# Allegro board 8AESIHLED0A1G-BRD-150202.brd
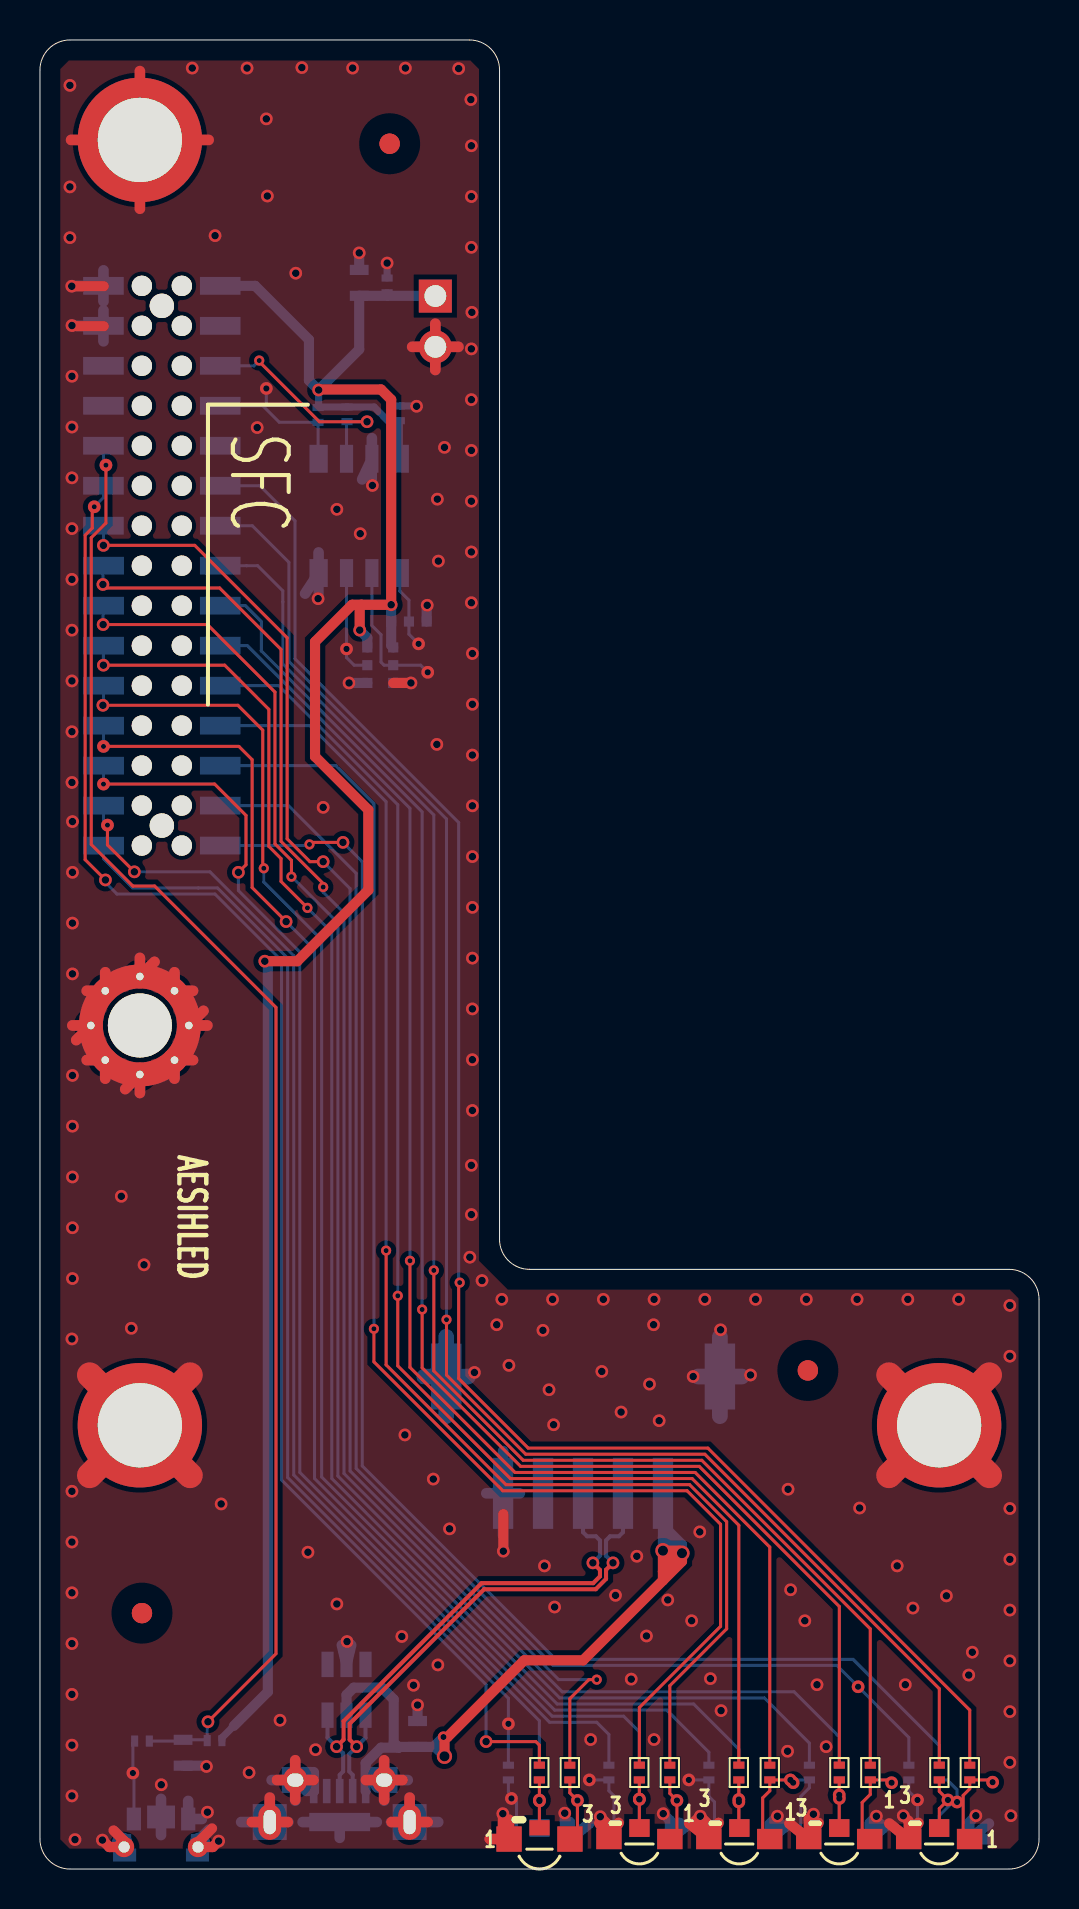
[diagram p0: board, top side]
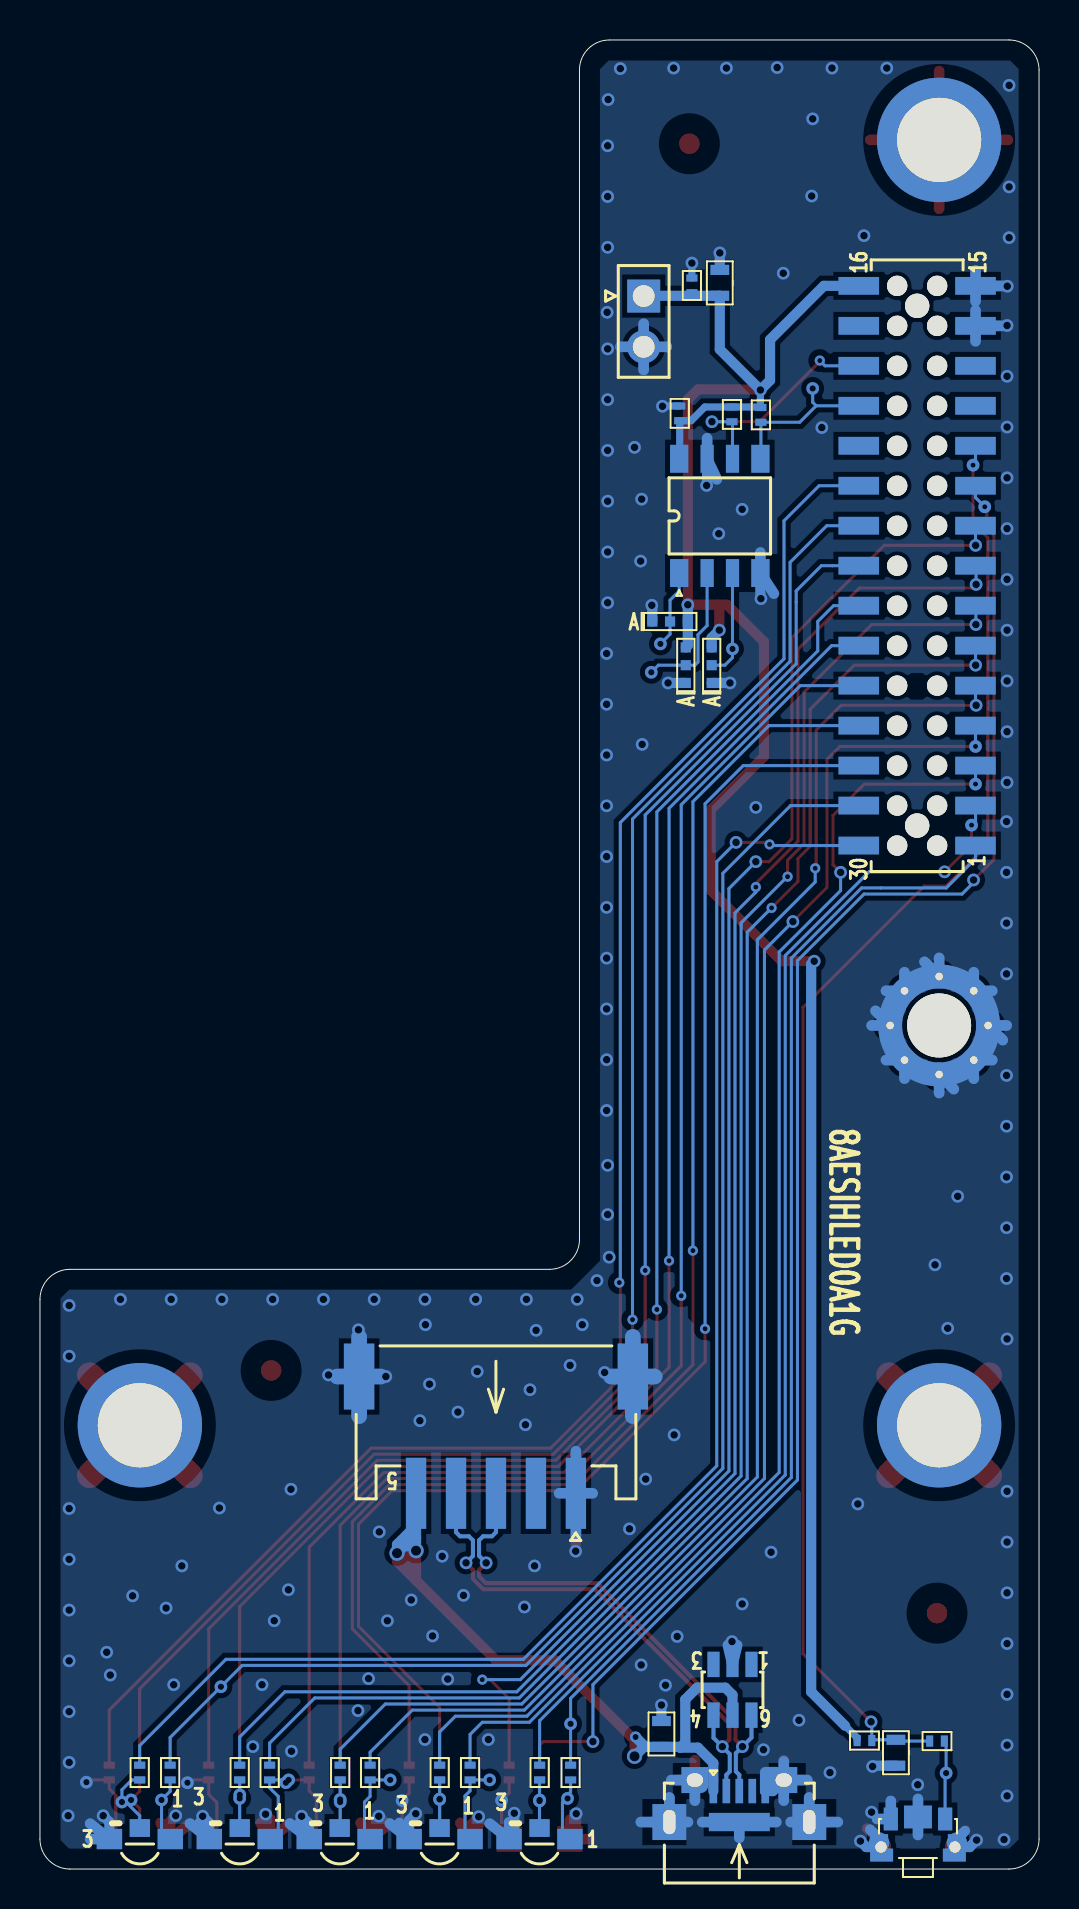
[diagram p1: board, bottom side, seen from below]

Outline 50 x 91.5 mm; copper layers: TOP, BOTTOM. Coordinates in mm from the lower left corner of the outline.
Outline path: 0,90 0,1.5 arc(0.44,0.44) 1.5,0 48.5,0 arc(49.56,0.44) 50,1.5 50,28.5 arc(49.56,29.56) 48.5,30 24.5,30 arc(23.44,30.44) 23,31.5 23,90 arc(22.56,91.06) 21.5,91.5 1.5,91.5 arc(0.44,91.06) 0,90

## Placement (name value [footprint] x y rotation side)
A1  3.5mm_8via  [A126_FG]  5 42.2 0 top
B1  Optics  [2B]  17.5 86.31 0 top
B2  Optics  [2B]  38.43 24.94 0 top
B3  Optics  [2B]  5.11 12.8 0 top
C1  10uF 6.3V***  [C0603]  15.98 79.35 270 bottom
C2  0.1u 16V***  [C0402]  17.37 79.22 270 bottom
C3  0.1u 16V***  [C0402]  17.98 72.82 270 bottom
C4  0.1uF 25V  [C0603]  18.9 6.76 90 bottom
C5  1uF 25V  [C0603]  7.16 5.82 270 bottom
D1  LED (Y/G)  [LED_LG110]  30 1.5 0 top
D2  LED (Y/G)  [LED_LG110]  35 1.5 0 top
D3  LED (Y/G)  [LED_LG110]  40 1.5 0 top
D4  LED (Y/G)  [LED_LG110]  45 1.5 0 top
D5  KPBVA-3010QBDCGKC  [KPBA_3010_A]  25 1.5 0 top
D6  LED (Y/G)  [LED_LG110]  35 1.5 180 bottom
D7  LED (Y/G)  [LED_LG110]  30 1.5 180 bottom
D8  LED (Y/G)  [LED_LG110]  25 1.5 180 bottom
D9  LED (Y/G)  [LED_LG110]  45 1.5 180 bottom
D10  LED (Y/G)  [LED_LG110]  40 1.5 180 bottom
J1  1K 5% 1/16W***  [JP3_0402]  18.47 62.41 180 bottom
J2  1K 5% 1/16W***  [JP3_0402]  17.68 60.22 90 bottom
J3  1K 5% 1/16W***  [JP3_0402]  16.38 60.22 90 bottom
JP1  **HEADER PIN C2(S)  [JP2]  19.79 78.69 270 bottom
JP2  HEADER PIN 2*15  [IC_JP2X15_2P0_SMD]  5.1 51.2 90 bottom
JP3  WAFER PIN 5P  [P200_5_R_SMT]  27.18 21.84 0 bottom
NOREF  -  []  8.41 73.25 270 top
NOREF#2  -  []  -46.9 94.25 0 top
NOREF#3  -  []  10.52 23.39 90 top
NOREF#4  -  []  0 0 0 top
O1  3.5mm_8via  [PAD_C245D166]  5 86.5 180 bottom
O2  3.5mm_8via  [PAD_C245D166]  45 22.2 180 bottom
O3  3.5mm_8via  [PAD_C245D166]  5 22.2 180 bottom
P1  UN15111-N12A41-7H  [USB_MICRO_B_DIP_F]  15 2.35 180 bottom
R1  150 5% 1/16W  [R0402]  24.99 4.83 270 top
R2  150 5% 1/16W  [R0402]  26.52 4.83 270 top
R3  150 5% 1/16W  [R0402]  30 4.83 270 top
R4  150 5% 1/16W  [R0402]  31.52 4.83 270 top
R5  150 5% 1/16W  [R0402]  34.98 4.83 270 top
R6  150 5% 1/16W  [R0402]  36.53 4.83 270 top
R7  150 5% 1/16W  [R0402]  40.01 4.83 270 top
R8  150 5% 1/16W  [R0402]  41.55 4.83 270 top
R9  150 5% 1/16W  [R0402]  45.01 4.83 270 top
R10  150 5% 1/16W  [R0402]  46.53 4.83 270 top
R11  4.7K 5% 1/16W***  [R0402]  15.37 72.77 270 bottom
R12  4.7K 5% 1/16W***  [R0402]  13.92 72.75 270 bottom
R13  1K 5% 1/16W  [R0402]  8.74 6.43 180 bottom
R14  150 5% 1/16W  [R0402]  45.01 4.83 270 bottom
R15  150 5% 1/16W  [R0402]  43.48 4.83 270 bottom
R16  150 5% 1/16W  [R0402]  40.01 4.83 270 bottom
R17  150 5% 1/16W  [R0402]  38.51 4.83 270 bottom
R18  150 5% 1/16W  [R0402]  34.98 4.83 270 bottom
R19  150 5% 1/16W  [R0402]  33.48 4.83 270 bottom
R20  150 5% 1/16W  [R0402]  30 4.83 270 bottom
R21  150 5% 1/16W  [R0402]  28.47 4.83 270 bottom
R22  150 5% 1/16W  [R0402]  24.99 4.83 270 bottom
R23  150 5% 1/16W  [R0402]  23.44 4.83 270 bottom
R24  68R 5% 1/16W  [R0402]  5.11 6.4 180 bottom
SW1  TSS00-EG-200-T28  [SW_TS_308GS]  6.06 1.53 180 bottom
U1  AT24C02D-SSHM-T***  [SOP8_1P27_6]  15.98 67.69 180 bottom
U2  SRV05-4  [SOT_26]  15.34 8.97 0 bottom

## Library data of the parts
A1 = SCREW HOLE_6: Tolerance: ***; User Part Number: ***; room: SCREW
B1-B3 = Optics_solder: Tolerance: ***; User Part Number: ***
C1-C4 = CAP_NP: Tolerance: ***; User Part Number: ***
C5 = CAP_NP: Tolerance: ***; User Part Number: ***; room: CPU_3_3V
D1-D4 D6-D10 = LED2A_1_4: Tolerance: ***; User Part Number: ***
D5 = LED2A_1_3: Tolerance: ***; User Part Number: ***
J1-J3 = JP3_0603: Tolerance: ***; User Part Number: ***
JP1 = JP2_0: Tolerance: ***; User Part Number: ***
JP2 = 30G2_0: Tolerance: ***; User Part Number: ***
JP3 = JP5_2: Tolerance: ***; User Part Number: ***
O1-O3 = SCREW HOLE_0: Tolerance: ***; User Part Number: ***; room: SCREW
P1 = UN15111_N12A41_7H: Tolerance: ***; User Part Number: ***
R1-R24 = R: Tolerance: ***; User Part Number: ***
SW1 = SW_BTS_1: Tolerance: ***; User Part Number: ***
U1 = AT24C512: Tolerance: ***; User Part Number: ***
U2 = SRV05: Tolerance: ***; User Part Number: ***

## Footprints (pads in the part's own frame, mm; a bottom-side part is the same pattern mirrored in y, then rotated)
2B
  round 1.016 smd: 1(0,0) 2(0,0)
A126_FG
  round 3.2 hole 3.2 unplated: (0,0)
  round 1.194 hole 0.381: 2(1.732,1.732) 3(-1.732,1.732) 4(-1.732,-1.732) 5(1.732,-1.732) 6(0,2.451) 7(0,-2.451) 8(-2.451,0) 9(2.451,0)
C0402
  rect 0.356x0.559 smd: 1(-0.368,0) 2(0.368,0)
C0603
  rect 0.508x0.94 smd: 1(-0.648,0) 2(0.648,0)
IC_JP2X15_2P0_SMD
  round 1.016 hole 1.016 unplated: (0,0) (0,2) (2,0) (2,2) (4,0) (4,2) (6,0) (6,2) (8,0) (8,2) (10,0) (10,2) (12,0) (12,2) (14,0) (14,2) (16,0) (16,2) (18,0) (18,2) (20,0) (20,2) (22,0) (22,2) (24,0) (24,2) (26,0) (26,2) (28,0) (28,2)
  round 1.219 hole 1.219 unplated: (1,1) (27,1)
  rect 0.889x2.032 smd: 1(0,-1.921) 2(2,-1.921) 3(4,-1.921) 4(6,-1.921) 5(8,-1.921) 6(10,-1.921) 7(12,-1.921) 8(14,-1.921) 9(16,-1.921) 10(18,-1.921) 11(20,-1.921) 12(22,-1.921) 13(24,-1.921) 14(26,-1.921) 15(28,-1.921) 16(28,3.921) 17(26,3.921) 18(24,3.921) 19(22,3.921) 20(20,3.921) 21(18,3.921) 22(16,3.921) 23(14,3.921) 24(12,3.921) 25(10,3.921) 26(8,3.921) 27(6,3.921) 28(4,3.921) 29(2,3.921) 30(0,3.921)
JP2
  rect 1.651x1.651 hole 1.092: 1(0,0)
  round 1.651 hole 1.092: 2(2.54,0)
JP3_0402
  rect 0.508x0.508 smd: 1(-0.889,0) 2(0,0) 3(0.889,0)
KPBA_3010_A
  rect 1.27x1.27 smd: 1(-1.524,0) 3(1.524,0)
  rect 1.016x0.762 smd: 2(0,0.559)
LED_LG110
  rect 1.27x1.016 smd: 1(1.524,0) 3(-1.524,0)
  rect 1.016x0.889 smd: 2(0,0.55)
P200_5_R_SMT
  rect 1.016x3.556 smd: 1(-4,3.048) 2(-2,3.048) 3(0,3.048) 4(2,3.048) 5(4,3.048)
  rect 1.524x3.302 smd: 6(6.85,-2.794) 7(-6.85,-2.794)
PAD_C245D166
  round 6.223 hole 4.216: 1(0,0)
R0402
  rect 0.356x0.559 smd: 1(-0.368,0) 2(0.368,0)
SOP8_1P27_6
  rect 0.914x1.397 smd: 1(-2.032,-2.857) 4(2.032,-2.857) 5(2.032,2.857) 8(-2.032,2.857)
  rect 0.66x1.397 smd: 2(-0.635,-2.857) 3(0.635,-2.857) 6(0.635,2.857) 7(-0.635,2.857)
SOT_26
  rect 0.61x1.27 smd: 1(-0.95,-1.27) 2(0,-1.27) 3(0.95,-1.27) 4(0.95,1.27) 5(0,1.27) 6(-0.95,1.27)
SW_TS_308GS
  rect 0.711x1.143 smd: 1(-1.36,0.978) 2(1.36,0.978)
  rect 1.397x1.143 smd: 3(0,1.079)
  round 1.016 hole 0.559: 4(-1.85,-0.425) 5(1.85,-0.425)
USB_MICRO_B_DIP_F
  rect 0.381x1.219 smd: 1(-1.3,1.55) 2(-0.65,1.55) 3(0,1.55) 4(0.65,1.55) 5(1.3,1.55)
  oval 1.168x1.321 hole 0.813x0.66: 6(-2.225,2.1) 7(2.225,2.1)
  oval 1.143x1.778 hole 0.61x1.219: 8(-3.5,0) 9(3.5,0)
  rect 3.048x0.914 smd: 10(0,0)

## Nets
3.3V: C1.2 C2.2 C3.2 J1.3 J2.3 J3.3 JP1.1 JP2.16 R11.1 R12.1 R13.1 U1.8(VCC)
GND: A1.2 A1.3 A1.4 A1.5 A1.6 A1.7 A1.8 A1.9 C1.1 C2.1 C3.1 C4.2 C5.2 D1.3 D2.3 D3.3 D4.3 D5.1 D6.3 D7.3 D8.3 D9.3 D10.3 J1.1 J2.1 J3.1 JP1.2 JP2.14 JP2.15 JP3.1 JP3.6 JP3.7 O1.1 O2.1 O3.1 P1.5(GND#5) P1.6(GND#6) P1.7(GND#7) P1.8(GND#8) P1.9(GND#9) P1.10(GND#10) SW1.1 SW1.3 SW1.4 SW1.5 U1.4(GND) U1.7(TEST) U2.2(GND)
VBUS: C4.1 JP3.5 P1.1(VBUS) U2.5(VCC)
A0: J1.2 U1.1(A0)
A1: J2.2 U1.2(A1)
A2: J3.2 U1.3(A2)
FP_LED0_B: JP2.10 R1.1
FP_LED0_G: JP2.9 R2.1
FP_LED1_G: JP2.2 R22.1
FP_LED1_Y: JP2.1 R23.1
FP_LED2_G: JP2.28 R3.1
FP_LED2_Y: JP2.27 R4.1
FP_LED3_G: JP2.4 R20.1
FP_LED3_Y: JP2.3 R21.1
FP_LED4_G: JP2.26 R5.1
FP_LED4_Y: JP2.25 R6.1
FP_LED5_G: JP2.6 R18.1
FP_LED5_Y: JP2.5 R19.1
FP_LED6_G: JP2.24 R7.1
FP_LED6_Y: JP2.23 R8.1
FP_LED7_G: JP2.8 R16.1
FP_LED7_Y: JP2.7 R17.1
FP_LED8_G: JP2.22 R9.1
FP_LED8_Y: JP2.21 R10.1
FP_LED9_G: JP2.30 R14.1
FP_LED9_Y: JP2.29 R15.1
FP_TACH_PB: C5.1 JP2.11 R13.2 R24.1
I2C_SCL_FP: JP2.18 R11.2 U1.6(SCL)
I2C_SDA_FP: JP2.19 R12.2 U1.5(SDA)
LED0_B: D5.2 R1.2
LED0_G: D5.3 R2.2
LED1_G: D8.2 R22.2
LED1_Y: D8.1 R23.2
LED2_G: D1.2 R3.2
LED2_Y: D1.1 R4.2
LED3_G: D7.2 R20.2
LED3_Y: D7.1 R21.2
LED4_G: D2.2 R5.2
LED4_Y: D2.1 R6.2
LED5_G: D6.2 R18.2
LED5_Y: D6.1 R19.2
LED6_G: D3.2 R7.2
LED6_Y: D3.1 R8.2
LED7_G: D10.2 R16.2
LED7_Y: D10.1 R17.2
LED8_G: D4.2 R9.2
LED8_Y: D4.1 R10.2
LED9_G: D9.2 R14.2
LED9_Y: D9.1 R15.2
TACT: R24.2 SW1.2
USB_DN: JP3.4 P1.2(DM) U2.4(I/O3)
USB_DP: JP3.3 P1.3(DP) U2.6(I/O4)

Pads without a net: B1 1 2; B2 1 2; B3 1 2; JP2 12 13 17 20; JP3 2; P1 4; U2 1 3

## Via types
v1: diameter 0.635, hole 0.318, TOP to BOTTOM, 27 vias
v2: diameter 0.635, hole 0.381, TOP to BOTTOM, 197 vias
v3: diameter 0.635, hole 0.254, TOP to BOTTOM, 5 vias
v4: diameter 0.508, hole 0.254, TOP to BOTTOM, 15 vias
v5: diameter 0.762, hole 0.508, TOP to BOTTOM, 3 vias
v6: diameter 0.559, hole 0.305, TOP to BOTTOM, 1 via

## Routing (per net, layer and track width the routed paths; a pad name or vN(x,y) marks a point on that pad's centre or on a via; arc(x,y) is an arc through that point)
3.3V: length 108.3
  TOP w0.508: v2(11.25,45.42) 12.88,45.42 16.43,48.97 16.43,52.98 13.77,55.65 13.77,61.39 15.62,63.25 16.08,63.25 ; v2(13.94,73.99) 13.97,74.02 17.07,74.02 17.58,73.51 v2(17.58,63.25) 16.08,63.25 ; 16.08,63.25 16,63.17 v2(16,61.98)
  BOTTOM w0.356: 13.94,73.14 R11.1 16.73,73.14 17.41,72.45 C3.2 17.98,70.57 ; 13.94,73.14 R12.1 ; 13.94,73.14 v2(13.94,73.99) ; C2.2 17.37,78.73 17.4,78.7 ; R13.1 9.11,6.57 9.7,7.16
  BOTTOM w0.508: JP2.16 10.77,79.2 13.46,76.5 13.46,74.47 v2(13.94,73.99) 15.98,76.02 C1.2 19.77,78.7 JP1.1 ; J2.3 17.58,61.21 J1.3 v2(17.58,63.25) ; 9.7,7.16 11.4,8.86 11.4,45.26 v2(11.25,45.42) ; v2(16,61.98) 16.38,61.59 J3.3 ; 17.98,70.57 U1.8
GND: length 212.4
  TOP w0.152: 33.48,1.78 32.94,2.31
  TOP w0.508: v2(43.21,2.67) 43.48,2.4 D4.3 ; 3.19,79.18 v2(1.59,79.18) ; v2(23.16,2.77) 23.16,1.81 D5.1 ; v2(38.71,2.74) 38.48,2.51 D3.3 ; 23.19,17.75 v2(23.19,15.9) ; 3.68,1.93 4.21,1.4 SW1.5 3.47,1.1 v2(3.12,1.45) ; J2.1 v2(18.57,59.33) ; 8.61,2.03 7.91,1.33 SW1.4 8.64,1.1 v2(8.94,1.4) ; v2(1.6,77.22) 1.64,77.18 3.19,77.18 ; D2.3 33.48,2.21 v2(33.05,2.64) ; v2(28.04,2.62) 28.48,2.18 D1.3
  TOP w0.533: v2(33.05,2.64) 32.68,2.27 32.51,2.27 D2.3 33.96,2.31 ; P1.6 17.23,5.44 ; P1.6 17.23,3.46 ; P1.6 16.31,4.45 ; P1.6 18.14,4.45 ; P1.9 11.5,3.57 ; P1.9 10.6,2.35 ; P1.9 12.4,2.35 ; 8.18,42.93 A1.9 8.38,42.2 ; 2.34,43.93 A1.3 3.27,44.86 ; 5,38.82 A1.7 4.27,39.02 ; 2.34,40.47 A1.4 3.27,39.54 ; JP1.2 19.79,77.31 ; JP1.2 20.94,76.15 ; JP1.2 19.79,74.99 ; JP1.2 18.63,76.15 ; O1.1 8.44,86.5 ; O1.1 5,83.06 ; O1.1 1.56,86.5 ; O1.1 5,89.94 ; 37.51,2.27 D3.3 38.96,2.31 ; 1.62,42.2 A1.8 1.82,41.47 ; 7.66,43.93 A1.2 6.73,44.86 ; P1.8 18.5,3.57 ; P1.8 17.6,2.35 ; P1.8 19.4,2.35 ; 11.86,4.45 P1.7 ; P1.7 12.78,3.46 ; P1.7 12.78,5.44 ; P1.7 13.69,4.45 ; 43.96,2.31 D4.3 42.51,2.27 ; 7.66,40.47 A1.5 6.73,39.54 ; 22.51,1.5 D5.1 23.48,2.47 ; 27.99,2.31 D1.3 28.96,2.31 ; 5,45.58 A1.6 5.73,45.38
  TOP w1.27: O2.1 47.51,24.71 ; O2.1 42.49,24.71 ; O2.1 47.51,19.69 ; O2.1 42.49,19.69 ; O3.1 7.51,19.69 ; O3.1 7.51,24.71 ; O3.1 2.49,24.71 ; O3.1 2.49,19.69
  BOTTOM w0.356: C3.1 18.83,73.19 v2(18.85,73.18) ; C2.1 v2(17.37,80.34)
  BOTTOM w0.508: P1.5 13.33,3.9 P1.7 ; C1.1 v2(15.98,80.85) ; v2(13.92,63.55) 13.94,63.58 U1.4 ; J1.1 19.35,63.2 v2(19.38,63.22) ; v2(36.91,2.64) 36.52,2.26 D6.3 ; J2.1 v2(18.57,59.33) ; 3.71,1.91 4.21,1.4 SW1.5 3.47,1.1 v2(3.12,1.45) ; v2(15.37,11.38) 15.34,11.35 U2.2 ; C5.2 8.29,5.17 v2(8.33,5.13) ; v2(8.94,1.4) 8.64,1.1 SW1.4 7.91,1.43 8.46,1.98 ; v2(16.64,69.22) 16.61,69.24 U1.7 ; v2(31.19,2.77) 31.52,2.44 D7.3 ; C4.2 v2(18.9,8.2) ; D10.3 41.52,2.31 v2(41.86,2.64) ; D8.3 26.26,1.76 v2(26.26,2.79) ; J3.1 v2(15.47,59.33) 15.44,59.36 ; D9.3 46.52,2.35 v2(46.84,2.67) ; 23.18,15.91 v2(23.19,15.9)
  BOTTOM w0.533: 6.73,39.54 A1.5 7.66,40.47 ; 19.79,74.99 JP1.2 ; JP1.2 19.79,77.31 ; JP1.2 18.63,76.15 ; JP1.2 20.94,76.15 ; 18.41,4.45 P1.6 17.23,3.42 ; 6.06,1.7 SW1.3 6.06,3.51 ; P1.9 11.5,3.58 ; P1.9 12.43,2.35 ; P1.9 10.07,2.35 ; 13.27,63.8 U1.4 13.94,65.86 ; JP2.15 3.18,79.98 ; JP2.15 3.18,78.42 ; JP2.15 1.83,79.2 ; JP2.14 3.18,77.98 ; JP2.14 1.83,77.2 ; JP2.14 3.18,76.42 ; 1.62,42.2 A1.8 1.82,41.47 ; 5,38.82 A1.7 4.27,39.02 ; P1.8 18.5,3.58 ; P1.8 19.93,2.35 ; P1.8 17.57,2.35 ; 3.27,44.86 A1.3 2.34,43.93 ; 32.01,2.31 D7.3 32.49,2.27 ; 8.18,42.93 A1.9 8.38,42.2 ; 42.01,2.31 D10.3 42.49,2.27 ; 26.52,2.34 D8.3 27.49,2.27 ; P1.10 16.85,2.35 ; P1.10 13.15,2.35 ; P1.10 15,1.56 ; JP3.1 23.18,20.9 ; JP3.1 24.02,18.8 ; JP3.1 22.34,18.8 ; JP3.1 23.18,16.69 ; 16.61,71.58 U1.7 16.12,69.52 ; 12.78,3.42 P1.7 ; P1.7 11.59,4.45 ; P1.7 13.17,4.84 13.55,4.84 P1.5 13.7,4.84 ; P1.7 12.78,5.38 ; 7.66,43.93 A1.2 6.73,44.86 ; 47.49,1.5 D9.3 47.49,2.27 ; 7.42,3.41 SW1.1 8.1,2.5 ; 2.34,40.47 A1.4 3.27,39.54 ; 37.01,2.31 D6.3 37.49,2.27 ; 15.11,11.2 U2.2 15.57,11.2 ; 5,45.58 A1.6 5.73,45.38
  BOTTOM w0.787: JP3.7 20.33,26.62 ; JP3.7 21.42,24.64 ; JP3.7 20.33,22.66 ; JP3.7 19.24,24.64 ; 34.03,22.66 JP3.6 ; JP3.6 32.94,24.64 ; JP3.6 34.03,26.62 ; JP3.6 35.12,24.64
  vias: v2(1.5,89.23) v2(1.5,84.15) v2(1.5,81.61) v2(1.6,74.68) v2(1.6,72.14) v2(1.6,69.6) v2(1.6,67.06) v2(1.6,64.52) v2(1.6,61.98) v2(1.6,59.44) v2(1.6,56.9) v2(1.6,54.36) v2(1.63,52.4) v2(1.63,49.86) v2(1.63,47.32) v2(1.63,44.78) v2(1.63,39.7) v2(1.63,37.16) v2(1.63,34.62) v2(1.63,32.08) v2(1.63,29.54) v2(1.6,26.52) v2(1.6,18.9) v2(1.6,16.36) v2(1.6,13.82) v2(1.6,11.28) v2(1.6,8.74) v2(1.6,6.2) v2(1.6,3.66) v2(1.75,1.47) v2(4.07,33.66) v2(4.57,27.05) v2(5.21,30.23) v2(6.07,4.22) v2(7.62,90.09) v2(8.38,2.84) v2(8.76,81.71) v2(9.07,18.26) v2(10.36,90.09) v2(10.46,4.83) v2(10.87,72.11) v2(11.33,87.55) v2(11.38,83.69) v2(12.01,7.44) v2(12.8,79.83) v2(13.11,90.12) v2(13.41,15.85) v2(13.79,5.97) v2(14.17,53.11) v2(14.86,68.02) v2(14.86,13.26) v2(15.65,90.09) v2(16.03,66.8) v2(18.11,11.63) v2(18.29,90.09) v2(18.26,21.72) v2(18.69,9.19) v2(19.68,19.51) v2(19.89,68.53) v2(19.94,65.43) v2(19.86,56.26) v2(19.91,10.21) v2(20.24,71.12) v2(20.5,17.02) v2(20.95,90.07) v2(21.51,30.61) v2(21.56,88.52) v2(21.59,86.21) v2(21.59,83.67) v2(21.59,81.13) v2(21.62,77.88) v2(21.59,76.05) v2(21.59,73.51) v2(21.59,70.97) v2(21.59,68.43) v2(21.59,65.89) v2(21.59,63.35) v2(21.64,60.81) v2(21.64,58.27) v2(21.64,55.73) v2(21.64,53.19) v2(21.64,50.65) v2(21.64,48.11) v2(21.64,45.57) v2(21.64,43.03) v2(21.64,40.49) v2(21.64,37.95) v2(21.59,35.2) v2(21.59,32.74) v2(21.74,24.84) v2(22.12,29.44) v2(22.86,27.23) v2(23.11,28.5) v2(23.47,25.2) v2(25.17,26.95) v2(25.25,15.16) v2(25.48,23.98) v2(25.65,28.5) v2(25.7,22.23) v2(25.76,13.11) v2(27.56,6.48) v2(28.12,24.89) v2(28.19,28.5) v2(28.8,13.69) v2(29.08,22.86) v2(29.59,9.5) v2(29.87,15.65) v2(30.35,11.66) v2(30.51,24.26) v2(30.73,28.5) v2(30.71,27.23) v2(30.73,6.48) v2(30.99,22.43) v2(31.42,13.46) v2(32.61,12.42) v2(32.69,24.64) v2(33.02,16.87) v2(33.27,28.5) v2(33.55,9.53) v2(34.06,26.97) v2(34.09,7.92) v2(35.56,24.71) v2(35.81,28.5) v2(37.44,19) v2(37.41,5.89) v2(37.57,13.97) v2(38.28,12.42) v2(38.35,28.5) v2(38.89,9.22) v2(39.34,6.12) v2(40.89,28.5) v2(41.02,18.06) v2(42.9,15.16) v2(43.31,9.22) v2(43.43,28.5) v2(43.69,13.06) v2(45.36,13.67) v2(45.97,28.5) v2(46.48,9.7) v2(46.66,10.85) v2(48.54,28.19) v2(48.54,25.65) v2(48.54,18.03) v2(48.54,15.49) v2(48.54,12.95) v2(48.54,10.41) v2(48.54,7.87) v2(48.54,5.33) v2(48.59,2.67)
VBUS: length 40.1
  TOP w0.508: 31.62,15.29 31.21,14.88 31.18,14.88 ; 31.62,15.29 31.62,15.85 ; 31.62,15.29 v5(32.13,15.8) ; v5(32.13,15.8) 32.01,15.93 v5(31.18,15.93) 31.18,14.88 ; v5(32.13,15.8) 32.13,15.39 31.18,14.44 ; 31.18,14.88 31.18,14.44 ; 31.18,14.44 27.18,10.44 24.23,10.44 20.4,6.6 v6(20.19,6.6) 20.24,6.55 v5(20.24,5.64)
  BOTTOM w0.508: 17.96,6.07 18,6.11 C4.1 19.7,6.11 ; 17.96,6.07 17.7,6.32 17.7,8.48 17.12,9.07 15.7,9.07 15.34,8.71 U2.5 ; 17.96,6.07 17.07,6.07 16.3,5.3 P1.1 ; JP3.5 31.18,17.18 ; 31.18,17.18 32.13,16.23 v5(32.13,15.8) 31.78,16.15 31.6,16.15 31.18,16.57 ; 31.18,17.18 31.18,16.57 ; 19.7,6.11 19.77,6.11 v5(20.24,5.64) ; 19.7,6.11 v6(20.19,6.6) ; 31.18,16.57 v5(31.18,15.93)
A0: length 3.9
  BOTTOM w0.152: U1.1 18.01,63.93 18.47,63.47 J1.2 18.47,61.77 v1(18.95,61.29)
A1: length 7.2
  BOTTOM w0.152: U1.2 16.61,62.2 17.07,61.75 17.07,60.38 17.22,60.22 J2.2 19.05,60.22 v1(19.41,59.87)
A2: length 5.4
  BOTTOM w0.152: U1.3 v1(15.34,61.04) 15.34,60.6 15.72,60.22 J3.2
FP_LED0_B: length 78.1
  TOP w0.152: v2(22.33,6.38) 24.82,6.38 24.99,6.2 R1.1 ; v3(2.72,68.15) 2.62,68.05 2.62,67.08 2.26,66.73 2.26,50.5 v2(3.28,49.48)
  BOTTOM w0.152: JP2.10 3.18,68.61 v3(2.72,68.15) ; v2(3.28,49.48) 3.28,49.35 3.85,48.77 8.76,48.77 12.09,45.44 12.09,19.46 22.33,9.22 v2(22.33,6.38)
FP_LED0_G: length 77.2
  TOP w0.152: v2(14.17,50.39) 13.51,50.39 12.37,51.54 12.37,61.59 7.75,66.22 v2(3.17,66.22) ; R2.1 26.52,8.52 27.47,9.47 v4(27.86,9.47)
  BOTTOM w0.152: v2(3.17,66.22) 3.18,66.22 JP2.9 ; v4(27.86,9.47) 25.96,9.47 15.52,19.91 15.52,49.05 v2(14.17,50.39)
FP_LED1_G: length 59.3
  TOP w0.152: v2(4.72,49.89) 3.38,51.23 v3(3.38,52.22)
  BOTTOM w0.152: v3(3.38,52.22) 3.18,52.42 JP2.2 ; R22.1 24.99,7.42 12.7,19.71 12.7,45.69 8.51,49.89 v2(4.72,49.89)
FP_LED1_Y: length 56.9
  BOTTOM w0.152: R23.1 v1(23.44,7.26) 23.44,8.54 12.4,19.59 12.4,45.57 8.88,49.08 7.92,49.08 4.64,49.08 3.18,50.54 JP2.1
FP_LED2_G: length 70.8
  TOP w0.152: v4(16.71,27.03) 16.71,25.37 23.16,18.92 32.38,18.92 34.06,17.25 34.06,12.14 30,8.08 R3.1
  BOTTOM w0.152: JP2.28 14.8,55.2 16.71,53.29 v4(16.71,27.03)
FP_LED2_Y: length 71.7
  TOP w0.152: v4(17.32,30.94) 17.32,25.22 23.32,19.23 32.51,19.23 34.37,17.37 34.37,12.01 31.52,9.17 R4.1
  BOTTOM w0.152: JP2.27 13.52,57.2 17.32,53.39 v4(17.32,30.94)
FP_LED3_G: length 69.2
  TOP w0.152: v2(12.32,47.4) 10.62,49.1 10.62,55.5 9.96,56.16 v3(3.18,56.16)
  BOTTOM w0.152: v2(12.32,47.4) 13.74,45.97 13.74,19.54 25.63,7.65 29.21,7.65 30,6.86 R20.1 ; JP2.4 v3(3.18,56.16)
FP_LED3_Y: length 65.4
  TOP w0.152: v3(3.18,54.28) 8.74,54.28 10.31,52.7 10.31,50.24 v2(9.93,49.86)
  BOTTOM w0.152: v2(9.93,49.86) 9.93,48.95 13,45.87 13,19.84 25.5,7.34 27.86,7.34 28.47,6.73 R21.1 ; JP2.3 v3(3.18,54.28)
FP_LED4_G: length 71.8
  TOP w0.152: R5.1 34.98,17.19 32.64,19.53 23.55,19.53 17.91,25.17 v4(17.91,28.68)
  BOTTOM w0.152: v4(17.91,28.68) 17.91,53.24 11.95,59.2 JP2.26
FP_LED4_Y: length 73.5
  TOP w0.152: v4(18.52,30.43) 18.52,25.1 23.77,19.84 32.79,19.84 36.53,16.1 R6.1
  BOTTOM w0.152: v4(18.52,30.43) 18.52,53.06 10.38,61.2 JP2.25
FP_LED5_G: length 76.7
  TOP w0.152: v4(13.39,48.08) 12.06,49.4 12.06,50.55 11.46,51.16 11.46,58.01 9.25,60.22 v2(3.17,60.22)
  BOTTOM w0.152: v4(13.39,48.08) 14.61,46.86 14.61,19.53 25.88,8.26 32.72,8.26 34.98,5.99 R18.1 ; JP2.6 3.17,61.2 v2(3.17,60.22)
FP_LED5_Y: length 73.8
  TOP w0.152: v4(11.2,50.06) 11.15,50.11 11.15,56.97 9.91,58.22 v2(3.15,58.22)
  BOTTOM w0.152: v2(3.15,58.22) 3.18,58.25 JP2.5 ; v4(11.2,50.06) 11.2,49.38 14.1,46.48 14.1,19.61 25.76,7.95 31.37,7.95 33.48,5.84 R19.1
FP_LED6_G: length 76.8
  TOP w0.152: v4(19.13,27.99) 19.13,25.07 24.06,20.14 32.99,20.14 40.01,13.13 R7.1
  BOTTOM w0.152: JP2.24 10.28,63.2 11.07,62.41 11.07,60.94 19.13,52.88 v4(19.13,27.99)
FP_LED6_Y: length 79.8
  TOP w0.152: R8.1 41.55,12.01 33.12,20.45 24.18,20.45 19.71,24.92 v4(19.71,29.95)
  BOTTOM w0.152: v4(19.71,29.95) 19.71,52.73 12.15,60.29 12.15,63.39 12.15,63.94 10.89,65.2 10.34,65.2 JP2.23
FP_LED7_G: length 85.4
  TOP w0.152: v2(3.15,64.26) 3.33,64.08 8.99,64.08 12.06,61.01 12.06,51.41 14.17,49.3 v4(14.17,49.12)
  BOTTOM w0.152: v4(14.17,49.12) 14.17,48.87 15.21,47.83 15.21,19.79 26.14,8.86 37.74,8.86 40.01,6.6 R16.1 ; v2(3.15,64.26) 3.15,65.17 JP2.8
FP_LED7_Y: length 81.7
  TOP w0.152: v2(3.16,62.26) 8.38,62.26 11.76,58.88 11.76,51.28 12.59,50.46 v4(12.59,49.64)
  BOTTOM w0.152: v2(3.16,62.26) 3.16,63.18 JP2.7 ; v4(12.59,49.64) 12.6,49.64 14.91,47.33 14.91,19.66 26.01,8.56 36.25,8.56 38.51,6.3 R17.1
FP_LED8_G: length 83.1
  TOP w0.152: R9.1 45.01,9.02 33.27,20.75 24.31,20.75 20.35,24.71 v4(20.35,27.48)
  BOTTOM w0.152: JP2.22 10.63,67.2 12.46,65.37 12.46,60.41 20.35,52.53 v4(20.35,27.48)
FP_LED8_Y: length 86
  TOP w0.152: R10.1 46.53,7.95 33.43,21.06 24.44,21.06 20.95,24.54 20.95,29.29 v4(21.01,29.34)
  BOTTOM w0.152: JP2.21 11.01,69.2 12.76,67.45 12.76,60.54 20.95,52.35 20.95,29.39 v4(21.01,29.34)
FP_LED9_G: length 73.5
  TOP w0.152: v4(13.49,51.26) 13.59,51.36 v2(15.16,51.36)
  BOTTOM w0.152: v4(13.49,51.26) 13.43,51.2 JP2.30 ; v2(15.16,51.36) 16.13,50.39 16.13,20.17 25.81,10.49 40.69,10.49 45.01,6.17 R14.1
FP_LED9_Y: length 72.6
  BOTTOM w0.152: R15.1 43.48,6.58 v1(40.94,9.12) 39.88,10.19 25.93,10.19 25.68,10.19 15.82,20.04 15.82,49.81 12.43,53.2 JP2.29
FP_TACH_PB: length 74
  TOP w0.152: v2(8.41,7.37) 11.81,10.77 11.81,43.1 5.74,49.17 4.65,49.17 2.57,51.26 2.57,66.6 3.3,67.34 v3(3.3,70.23)
  BOTTOM w0.152: v2(8.41,7.37) 8.41,7.16 8.37,7.12 R13.2 8.33,6.46 C5.1 7.1,6.4 R24.1 ; JP2.11 3.18,70.35 v3(3.3,70.23)
I2C_SCL_FP: length 11.6
  TOP w0.152: v4(10.97,75.46) 10.97,75.41 13.98,72.4 v2(16.37,72.4)
  BOTTOM w0.152: v4(10.97,75.46) 10.71,75.2 JP2.18 ; U1.6 15.34,72.38 R11.2 v2(16.37,72.4)
I2C_SDA_FP: length 8
  BOTTOM w0.152: 11.15,73.2 11.33,73.38 v1(11.33,74.07) ; 11.15,73.2 11.98,72.38 R12.2 13.92,70.57 U1.5 ; 11.15,73.2 JP2.19
LED0_B: length 2.4
  TOP w0.152: R1.2 v1(24.99,3.45) 24.99,2.07 D5.2
LED0_G: length 3.3
  TOP w0.152: D5.3 26.9,1.87 v1(26.9,3.43) 26.52,3.81 R2.2
LED1_G: length 2.4
  BOTTOM w0.152: D8.2 v1(25,3.4) 25,4.45 R22.2
LED1_Y: length 3.3
  BOTTOM w0.152: R23.2 23.44,3.86 23.6,3.71 v1(23.6,3.53) 23.67,3.53 23.85,3.35 23.85,1.88 23.48,1.5 D8.1
LED2_G: length 2.4
  TOP w0.152: R3.2 v1(30,3.51) 30,2.05 D1.2
LED2_Y: length 3.3
  TOP w0.152: R4.2 31.52,3.78 v1(31.88,3.43) 31.88,1.85 D1.1
LED3_G: length 2.4
  BOTTOM w0.152: R20.2 v1(30,3.48) 30,2.05 D7.2
LED3_Y: length 4.1
  BOTTOM w0.152: D7.1 28.73,1.75 28.73,3.66 28.47,3.91 R21.2 v1(27.5,4.46)
LED4_G: length 2.4
  TOP w0.152: R5.2 v1(34.98,3.48) 34.98,2.07 D2.2
LED4_Y: length 4.5
  TOP w0.152: D2.1 36.17,1.85 36.17,3.56 36.53,3.91 R6.2 37.55,4.46 v1(37.69,4.32)
LED5_G: length 2.4
  BOTTOM w0.152: D6.2 34.98,2.07 v1(34.98,3.35) R18.2
LED5_Y: length 4.2
  BOTTOM w0.152: v1(32.47,4.46) R19.2 33.48,3.63 33.76,3.35 33.76,1.78 D6.1
LED6_G: length 2.4
  TOP w0.152: D3.2 v1(40,3.71) 40,4.45 R7.2
LED6_Y: length 4.4
  TOP w0.152: v1(42.62,4.32) 42.48,4.46 R8.2 41.55,3.73 41.15,3.33 41.15,1.88 D3.1
LED7_G: length 2.4
  BOTTOM w0.152: D10.2 40.01,2.05 v1(40.01,3.53) R16.2
LED7_Y: length 4.3
  BOTTOM w0.152: v1(37.55,4.46) R17.2 38.51,4.06 38.07,3.63 38.07,1.9 D10.1
LED8_G: length 2.8
  TOP w0.152: R9.2 45.01,3.89 v1(45.44,3.45) 45.01,3.02 45.01,2.06 D4.2
LED8_Y: length 4.4
  TOP w0.152: v1(47.68,4.34) 47.56,4.46 R10.2 46.53,4.01 46.2,3.68 46.2,1.82 D4.1
LED9_G: length 3.5
  BOTTOM w0.152: R14.2 45.4,4.46 45.9,3.96 v1(45.9,3.35) 45.69,3.35 45.01,2.67 45.01,2.06 D9.2
LED9_Y: length 3.3
  BOTTOM w0.152: D9.1 43.92,1.94 v1(43.92,3.45) 43.48,3.89 R15.2
TACT: length 4
  BOTTOM w0.152: R24.2 4.65,6.31 v1(4.65,4.8) 4.7,4.75 4.7,2.51 SW1.2
USB_DN: length 26.5
  TOP w0.203: v2(15.85,6.12) 15.5,6.47 15.5,7.27 22.23,14 27.81,14 28.33,14.51 28.33,14.97 v2(28.68,15.32)
  BOTTOM w0.203: U2.4 16.29,6.56 v2(15.85,6.12) 15.48,5.75 15.48,4.88 15.65,4.71 P1.2 ; JP3.4 29.18,16.85 28.97,16.65 28.53,16.65 28.33,16.44 28.33,15.66 v2(28.68,15.32)
USB_DP: length 26.5
  TOP w0.203: v2(27.67,15.32) 28.03,14.96 28.03,14.64 27.69,14.3 22.1,14.3 15.19,7.4 15.19,6.47 v2(14.84,6.12)
  BOTTOM w0.203: JP3.3 27.18,16.85 27.38,16.65 27.82,16.65 28.03,16.44 28.03,15.67 v2(27.67,15.32) ; U2.6 14.39,6.57 v2(14.84,6.12) 15.17,5.79 15.17,4.88 15,4.71 P1.3

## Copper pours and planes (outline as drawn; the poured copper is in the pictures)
GND on TOP (solid shape): outline of 222 points within 1.95,39.15 8.05,45.25
GND on BOTTOM (solid shape): outline of 222 points within 1.95,39.15 8.05,45.25
GND on TOP: 1.45,90.47 21.54,90.47 21.97,90.04 21.97,30.43 23.42,28.98 48.54,28.98 48.97,28.55 48.97,1.45 48.54,1.02 1.48,1.02 1.02,1.49 1.02,90.05 ; 29 cut-outs
GND on BOTTOM: 1.45,90.47 21.54,90.47 21.97,90.04 21.97,30.43 23.42,28.98 48.54,28.98 48.97,28.55 48.97,1.45 48.54,1.02 1.48,1.02 1.02,1.49 1.02,90.05 ; 24 cut-outs

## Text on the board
Ref Des/Silkscreen Top: AESIHLED
User.15: FIGURE | SIZE | 10.0 | 12.0 | 15.0 | 20.0 | 22.0 | 43.0 | 166.0 | 40.0 | 48.0 | 126.0 | 32.0x26.0 | 48.0x24.0 | DRILL CHART: TOP to BOTTOM | ALL UNITS ARE IN MILS | TOLERANCE | +3.0/-3.0 | +2.0/-2.0 | PLATED | NON-PLATED | QTY | 20 | 1 | 8 | 197 | 3 | 2 | 30
